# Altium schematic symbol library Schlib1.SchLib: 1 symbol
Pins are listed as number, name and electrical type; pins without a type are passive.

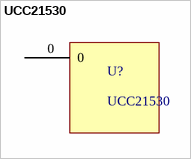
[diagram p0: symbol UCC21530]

## UCC21530
designator U?
pins: 0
